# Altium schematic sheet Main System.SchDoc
size A4
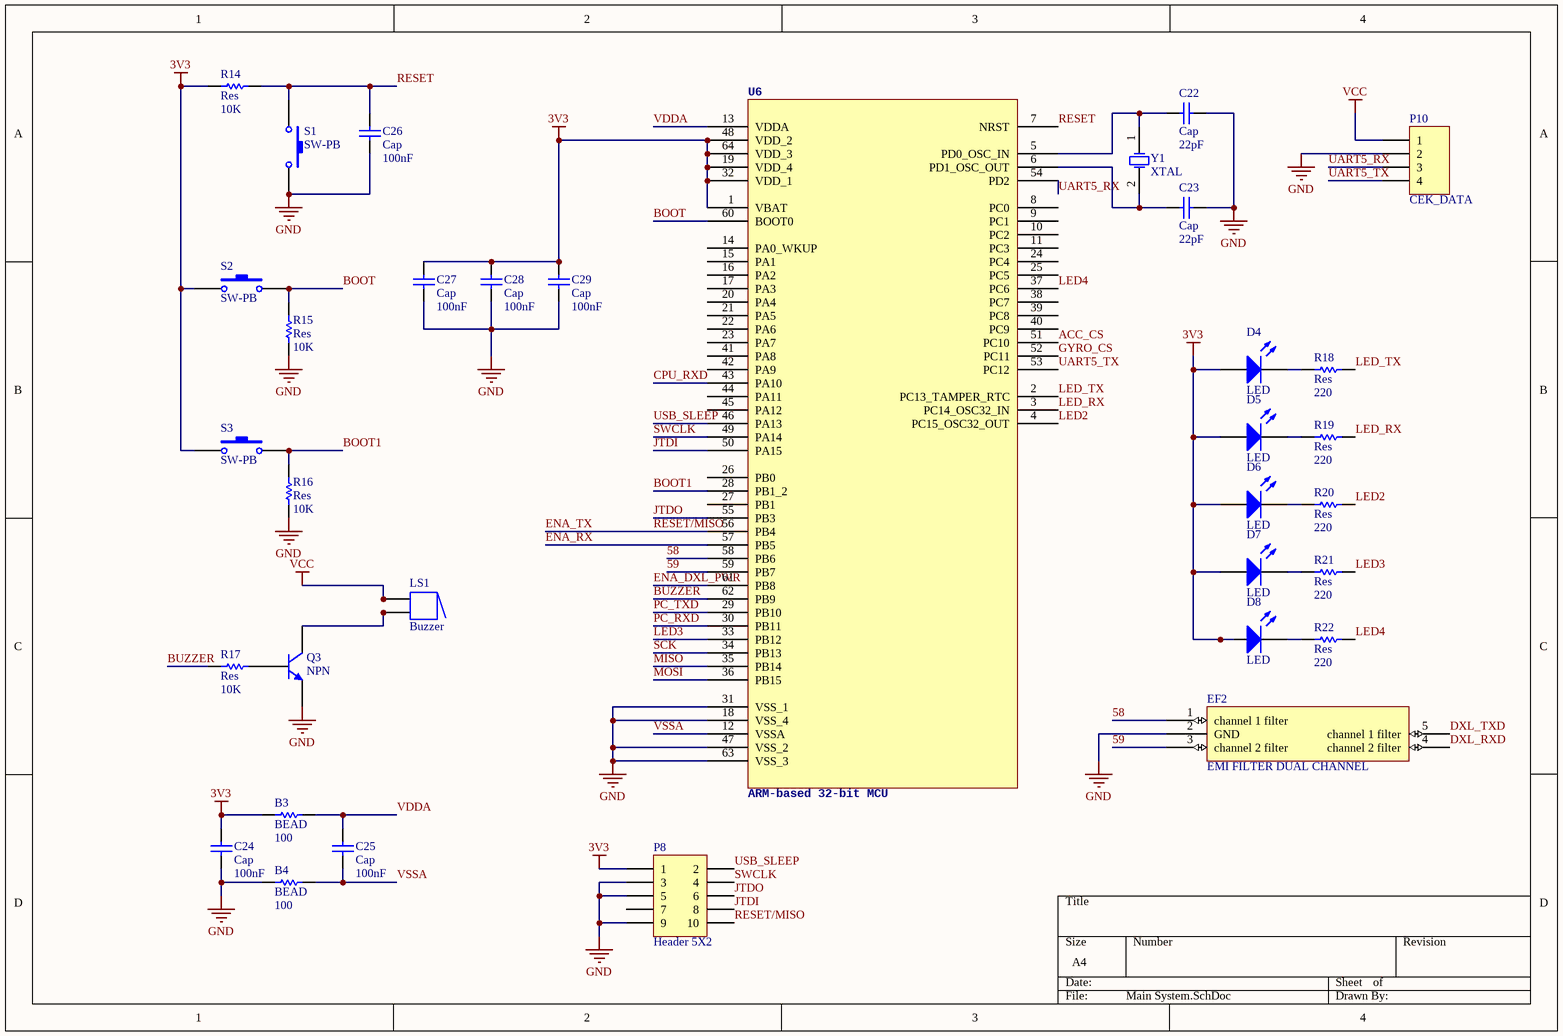
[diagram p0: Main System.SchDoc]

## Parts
B3  BEAD  value 100  [0603-RES]
B4  BEAD  value 100  [0603-RES]
C22  Cap  value 22pF  [0603-CAP]
C23  Cap  value 22pF  [0603-CAP]
C24  Cap  value 100nF  [0603-CAP]
C25  Cap  value 100nF  [0603-CAP]
C26  Cap  value 100nF  [0603-CAP]
C27  Cap  value 100nF  [0603-CAP]
C28  Cap  value 100nF  [0603-CAP]
C29  Cap  value 100nF  [0603-CAP]
D4  LED  [CHIPLED_0603]
D5  LED  [CHIPLED_0603]
D6  LED  [CHIPLED_0603]
D7  LED  [CHIPLED_0603]
D8  LED  [CHIPLED_0603]
EF2  EMI FILTER DUAL CHANNEL  [Emi Filter Dual Channel SOTFL]
LS1  Buzzer  [ABSM-1574]
P8  Header 5X2  [HDR2X5]
P10  CEK_DATA  [HDR1X4]
Q3  NPN  [SOT23]
R14  Res  value 10K  [0603-RES]
R15  Res  value 10K  [0603-RES]
R16  Res  value 10K  [0603-RES]
R17  Res  value 10K  [0603-RES]
R18  Res  value 220  [0603-RES]
R19  Res  value 220  [0603-RES]
R20  Res  value 220  [0603-RES]
R21  Res  value 220  [0603-RES]
R22  Res  value 220  [0603-RES]
S1  SW-PB  [TACTILE-SWITCH-SMD]
S2  SW-PB  [TACTILE-SWITCH-SMD]
S3  SW-PB  [TACTILE-SWITCH-SMD]
U6  ARM-based 32-bit MCU  [QFP-64N]
Y1  XTAL  [HC49US]

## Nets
3V3: B3.2 C24.2 C27.2 C28.2 C29.2 D4.1(A) D5.1(A) D6.1(A) D7.1(A) D8.1(A) P8.1 R14.1 S2.1 S3.1 U6.1(VBAT) U6.19(VDD_4) U6.32(VDD_1) U6.48(VDD_2) U6.64(VDD_3)
GND: B4.2 C22.2 C23.2 C24.1 C26.1 C27.1 C28.1 C29.1 EF2.2(GND) P8.3 P8.5 P8.9 P10.2 Q3.2(E) R15.1 R16.1 S1.3 U6.18(VSS_4) U6.31(VSS_1) U6.47(VSS_2) U6.63(VSS_3)
VCC: LS1.1 LS1.1A P10.1
58: EF2.1(channel_1_filter) U6.58(PB6)
59: EF2.3(channel_2_filter) U6.59(PB7)
ACC_CS: U6.51(PC10)
BOOT: R15.2 S2.3 U6.60(BOOT0)
BOOT1: R16.2 S3.3 U6.28(PB1_2)
BUZZER: R17.2 U6.62(PB9)
CPU_RXD: U6.43(PA10)
DXL_RXD: EF2.4(channel_2_filter)
DXL_TXD: EF2.5(channel_1_filter)
ENA_DXL_PWR: U6.61(PB8)
ENA_RX: U6.57(PB5)
ENA_TX: P8.10 U6.56(PB4)  [also labelled RESET/MISO]
GYRO_CS: U6.52(PC11)
JTDI: P8.8 U6.50(PA15)
JTDO: P8.6 U6.55(PB3)
LED2: R20.1 U6.4(PC15_OSC32_OUT)
LED3: R21.1 U6.33(PB12)
LED4: R22.1 U6.37(PC6)
LED_RX: R19.1 U6.3(PC14_OSC32_IN)
LED_TX: R18.1 U6.2(PC13_TAMPER_RTC)
MISO: U6.35(PB14)
MOSI: U6.36(PB15)
PC_RXD: U6.30(PB11)
PC_TXD: U6.29(PB10)
RESET: C26.2 R14.2 S1.1 U6.7(NRST)
SCK: U6.34(PB13)
SWCLK: P8.4 U6.49(PA14)
UART5_RX: P10.3 U6.54(PD2)
UART5_TX: P10.4 U6.53(PC12)
USB_SLEEP: P8.2 U6.46(PA13)
VDDA: B3.1 C25.2 U6.13(VDDA)
VSSA: B4.1 C25.1 U6.12(VSSA)
NetC22_1: C22.1 U6.5(PD0_OSC_IN) Y1.1(OSC1)
NetC23_1: C23.1 U6.6(PD1_OSC_OUT) Y1.2(OSC2)
NetD4_2: D4.2(K) R18.2
NetD5_2: D5.2(K) R19.2
NetD6_2: D6.2(K) R20.2
NetD7_2: D7.2(K) R21.2
NetD8_2: D8.2(K) R22.2
NetLS1_2: LS1.2 LS1.2A Q3.3(C)
NetQ3_1: Q3.1(B) R17.1

Not connected (* = marked no-connect by the designer): P8 7; U6 8(PC0) 9(PC1) 10(PC2) 11(PC3) 14(PA0_WKUP) 15(PA1) 16(PA2) 17(PA3) 20(PA4) 21(PA5) 22(PA6) 23(PA7) 24(PC4) 25(PC5) 26(PB0) 27(PB1) 38(PC7) 39(PC8) 40(PC9) 41(PA8) 42(PA9) 44(PA11) 45(PA12)

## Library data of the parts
B3 B4 R14-R22 = Res: Resistor
C22-C29 = Cap: Capacitor
D4-D8 = LED: Typical INFRARED GaAs LED
LS1 = Buzzer: Magnetic Transducer Buzzer
P8 = Header 5X2: Header, 5-Pin, Dual row
P10 = Header 4: Header, 4-Pin
Q3 = NPN: NPN Bipolar Transistor
S1-S3 = SW-PB: Switch
U6 = STM32F103RET6
Y1 = XTAL: Crystal Oscillator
